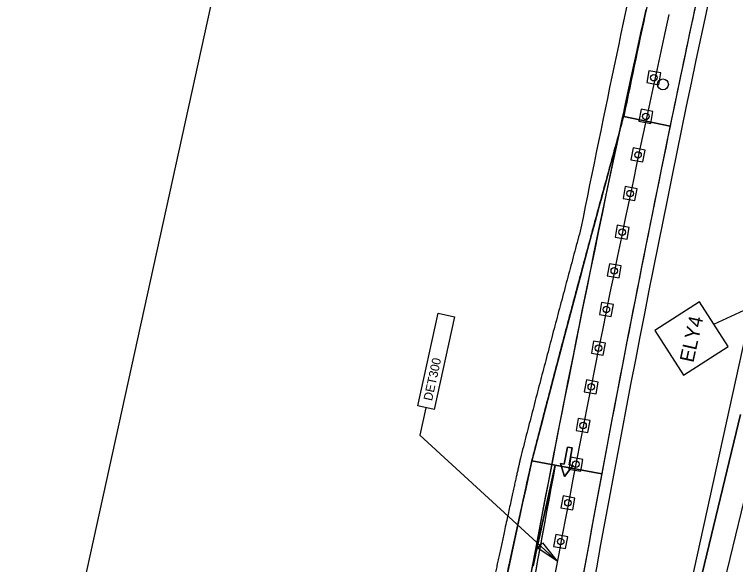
# Model space of a CAD drawing. Extents: x 14104283 to 14121738, y 8635219 to 8671666.
# Drawn here: x 14107783.5 to 14108149.2, y 8640616.4 to 8640895.4 of the extents above; entities that cross this region are included whole.
import ezdxf

# ---------------------------------------------------------------- set-up
doc = ezdxf.new("R2010")
doc.units = 0
for name, color, linetype in [('Cell', 7, 'Continuous'), ('Default', 7, 'Continuous'), ('dsnNonPlotable', 7, 'Continuous'), ('dsnPaintExistingBrokenLaneLineWhite', 7, 'Continuous'), ('dsnPaintExistingEdgeLineRightWhite', 7, 'Continuous'), ('dsnStdLabel', 7, 'Continuous'), ('dsnStgShadingPrevPav', 7, 'Continuous'), ('dsnTapePlaceChannelizingLaneWhite', 7, 'Continuous'), ('dsnTapePlaceChannelizingLaneYellow', 7, 'Continuous'), ('Text', 7, 'Continuous')]:
    doc.layers.add(name, color=color, linetype=linetype)

msp = doc.modelspace()

# ---------------------------------------------------------------- linework, layer by layer
at = {"layer": 'Cell'}
for points in [[(14108110.21, 8640859.76), (14108111.29, 8640865.79), (14108105.26, 8640866.87), (14108104.18, 8640860.84), (14108110.21, 8640859.76)], [(14108110.21, 8640859.76), (14108111.29, 8640865.79), (14108105.26, 8640866.87), (14108104.18, 8640860.84), (14108110.21, 8640859.76)], [(14108106.19, 8640840.17), (14108107.27, 8640846.2), (14108101.24, 8640847.28), (14108100.16, 8640841.25), (14108106.19, 8640840.17)], [(14108106.19, 8640840.17), (14108107.27, 8640846.2), (14108101.24, 8640847.28), (14108100.16, 8640841.25), (14108106.19, 8640840.17)], [(14108102.18, 8640820.58), (14108103.26, 8640826.61), (14108097.23, 8640827.69), (14108096.15, 8640821.66), (14108102.18, 8640820.58)], [(14108102.18, 8640820.58), (14108103.26, 8640826.61), (14108097.23, 8640827.69), (14108096.15, 8640821.66), (14108102.18, 8640820.58)], [(14108098.17, 8640800.98), (14108099.25, 8640807.01), (14108093.22, 8640808.09), (14108092.14, 8640802.06), (14108098.17, 8640800.98)], [(14108098.17, 8640800.98), (14108099.25, 8640807.01), (14108093.22, 8640808.09), (14108092.14, 8640802.06), (14108098.17, 8640800.98)], [(14108094.16, 8640781.39), (14108095.24, 8640787.42), (14108089.21, 8640788.5), (14108088.13, 8640782.47), (14108094.16, 8640781.39)], [(14108094.16, 8640781.39), (14108095.24, 8640787.42), (14108089.21, 8640788.5), (14108088.13, 8640782.47), (14108094.16, 8640781.39)], [(14108090.14, 8640761.8), (14108091.22, 8640767.83), (14108085.19, 8640768.91), (14108084.11, 8640762.88), (14108090.14, 8640761.8)], [(14108090.14, 8640761.8), (14108091.22, 8640767.83), (14108085.19, 8640768.91), (14108084.11, 8640762.88), (14108090.14, 8640761.8)], [(14108086.13, 8640742.2), (14108087.21, 8640748.23), (14108081.18, 8640749.31), (14108080.1, 8640743.28), (14108086.13, 8640742.2)], [(14108086.13, 8640742.2), (14108087.21, 8640748.23), (14108081.18, 8640749.31), (14108080.1, 8640743.28), (14108086.13, 8640742.2)], [(14108082.12, 8640722.61), (14108083.2, 8640728.64), (14108077.17, 8640729.72), (14108076.09, 8640723.69), (14108082.12, 8640722.61)], [(14108082.12, 8640722.61), (14108083.2, 8640728.64), (14108077.17, 8640729.72), (14108076.09, 8640723.69), (14108082.12, 8640722.61)], [(14108078.5, 8640702.94), (14108079.58, 8640708.97), (14108073.55, 8640710.05), (14108072.47, 8640704.02), (14108078.5, 8640702.94)], [(14108078.5, 8640702.94), (14108079.58, 8640708.97), (14108073.55, 8640710.05), (14108072.47, 8640704.02), (14108078.5, 8640702.94)], [(14108074.32, 8640683.37), (14108075.4, 8640689.4), (14108069.37, 8640690.48), (14108068.29, 8640684.45), (14108074.32, 8640683.37)], [(14108074.32, 8640683.37), (14108075.4, 8640689.4), (14108069.37, 8640690.48), (14108068.29, 8640684.45), (14108074.32, 8640683.37)], [(14108062.33, 8640667.36), (14108060.48, 8640667.69), (14108062.44, 8640660.99), (14108066.63, 8640666.58), (14108064.79, 8640666.91), (14108066.35, 8640675.52), (14108063.89, 8640675.97), (14108062.33, 8640667.36)], [(14108070.65, 8640663.71), (14108071.73, 8640669.74), (14108065.7, 8640670.82), (14108064.62, 8640664.79), (14108070.65, 8640663.71)], [(14108070.65, 8640663.71), (14108071.73, 8640669.74), (14108065.7, 8640670.82), (14108064.62, 8640664.79), (14108070.65, 8640663.71)], [(14108066.65, 8640644.12), (14108067.73, 8640650.15), (14108061.7, 8640651.22), (14108060.62, 8640645.2), (14108066.65, 8640644.12)], [(14108066.65, 8640644.12), (14108067.73, 8640650.15), (14108061.7, 8640651.22), (14108060.62, 8640645.2), (14108066.65, 8640644.12)], [(14108062.97, 8640624.46), (14108064.05, 8640630.49), (14108058.02, 8640631.57), (14108056.94, 8640625.54), (14108062.97, 8640624.46)], [(14108062.97, 8640624.46), (14108064.05, 8640630.49), (14108058.02, 8640631.57), (14108056.94, 8640625.54), (14108062.97, 8640624.46)]]:
    msp.add_lwpolyline(points, dxfattribs=at)
msp.add_lwpolyline([(14108063.89, 8640675.97), (14108066.35, 8640675.52), (14108064.79, 8640666.91), (14108066.63, 8640666.58), (14108062.44, 8640660.99), (14108060.48, 8640667.69), (14108062.33, 8640667.36)], close=True, dxfattribs=at)
for centre, radius in [((14108107.73, 8640863.32), 1.65), ((14108107.73, 8640863.32), 1.65), ((14108112.34, 8640859.94), 2.75), ((14108103.72, 8640843.72), 1.65), ((14108103.72, 8640843.72), 1.65), ((14108099.71, 8640824.13), 1.65), ((14108099.71, 8640824.13), 1.65), ((14108095.69, 8640804.54), 1.65), ((14108095.69, 8640804.54), 1.65), ((14108091.68, 8640784.94), 1.65), ((14108091.68, 8640784.94), 1.65), ((14108087.67, 8640765.35), 1.65), ((14108087.67, 8640765.35), 1.65), ((14108083.66, 8640745.76), 1.65), ((14108083.66, 8640745.76), 1.65), ((14108079.64, 8640726.16), 1.65), ((14108079.64, 8640726.16), 1.65), ((14108076.02, 8640706.49), 1.65), ((14108076.02, 8640706.49), 1.65), ((14108071.85, 8640686.93), 1.65), ((14108071.85, 8640686.93), 1.65), ((14108068.17, 8640667.27), 1.65), ((14108068.17, 8640667.27), 1.65), ((14108064.17, 8640647.67), 1.65), ((14108064.17, 8640647.67), 1.65), ((14108060.5, 8640628.01), 1.65), ((14108060.5, 8640628.01), 1.65)]:
    msp.add_circle(centre, radius, dxfattribs=at)
at = {"layer": 'Default'}
for p, q in [((14108151.72, 8640692.57), (14108081.5, 8640400.87)), ((14108093.19, 8640398.18), (14108163.38, 8640689.76))]:
    msp.add_line(p, q, dxfattribs=at)
for centre, radius, start, end in [((14117394.14, 8638857.08), 9512, 167.610212, 171.325989), ((14117394.14, 8638857.08), 9500, 167.610212, 171.325989), ((14117502.5, 8638839.63), 9621.75, 168.048489, 169.460498), ((14117245.13, 8638308.71), 9497.18, 164.591267, 165.609485), ((14117342.69, 8638609.63), 9522.13, 167.509575, 168.915877)]:
    msp.add_arc(centre, radius, start, end, dxfattribs=at)
at = {"layer": 'dsnNonPlotable'}
msp.add_lwpolyline([(14107651.31, 8639844.94), (14107987.7, 8641375.92), (14108480.93, 8641267.54), (14108144.54, 8639736.56)], close=True, dxfattribs=at)
at = {"layer": 'dsnPaintExistingBrokenLaneLineWhite'}
msp.add_arc((14117394.14, 8638857.08), 9500, 167.610212, 171.325989, dxfattribs=at)
at = {"layer": 'dsnPaintExistingEdgeLineRightWhite'}
for centre, radius, start, end in [((14117394.14, 8638857.08), 9512, 167.610212, 168.003119), ((14117245.13, 8638308.71), 9497.18, 164.578206, 165.609485), ((14117342.69, 8638609.63), 9522.13, 167.509575, 168.915877)]:
    msp.add_arc(centre, radius, start, end, dxfattribs=at)
at = {"layer": 'dsnStdLabel'}
msp.add_line((14108138.22, 8640738.34), (14108165.33, 8640750.93), dxfattribs=at)
msp.add_lwpolyline([(14108122.75, 8640712.41), (14108145.49, 8640726.96), (14108130.94, 8640749.71), (14108108.2, 8640735.16)], close=True, dxfattribs=at)
at = {"layer": 'dsnStgShadingPrevPav'}
for p, q in [((14108092.51, 8640843.67), (14108116.01, 8640838.82)), ((14108116.01, 8640838.82), (14108092.51, 8640843.67)), ((14108045.92, 8640669.04), (14108057.72, 8640666.84)), ((14108081.31, 8640662.43), (14108045.92, 8640669.04)), ((14108057.72, 8640666.84), (14108081.31, 8640662.43))]:
    msp.add_line(p, q, dxfattribs=at)
msp.add_lwpolyline([(14108081.5, 8640400.87), (14108123.34, 8640591.33), (14108126.55, 8640605.98), (14108216.67, 8641016.2), (14108268.16, 8641250.61), (14108382.95, 8641773.15), (14108422.02, 8641764.57), (14108309.38, 8641251.8), (14108270.22, 8641073.55), (14108265.93, 8641054.01), (14108255.74, 8641007.62), (14108202.1, 8640763.44), (14108120.56, 8640392.29)], close=True, dxfattribs=at)
for radius, start, end in [(9522, 167.610212, 168.688952), (9512, 167.610212, 168.328257), (9512, 167.610212, 168.328257), (9488, 167.610212, 172.222077), (9482, 167.610212, 172.222077), (9488, 167.610212, 168.328257), (9488, 168.328257, 169.413861), (9512, 169.413861, 172.222077), (9512, 169.413861, 170.574102), (9488, 169.413861, 172.222077)]:
    msp.add_arc((14117407.82, 8638919.35), radius, start, end, dxfattribs=at)
for points, degree in [([(14108045.92, 8640669.04), (14108046.67, 8640671.96), (14108048.17, 8640677.8), (14108050.43, 8640686.55), (14108052.7, 8640695.31), (14108054.98, 8640704.06), (14108057.26, 8640712.8), (14108059.55, 8640721.55), (14108061.85, 8640730.29), (14108064.16, 8640739.03), (14108066.48, 8640747.76), (14108068.81, 8640756.5), (14108071.14, 8640765.23), (14108073.48, 8640773.95), (14108075.83, 8640782.68), (14108078.19, 8640791.4), (14108080.55, 8640800.12), (14108082.93, 8640808.84), (14108085.31, 8640817.55), (14108087.7, 8640826.26), (14108090.1, 8640834.97), (14108091.7, 8640840.77), (14108092.51, 8640843.67)], 3), ([(14108045.92, 8640669.04), (14108046.67, 8640671.96), (14108048.17, 8640677.8), (14108050.43, 8640686.55), (14108052.7, 8640695.31), (14108054.98, 8640704.06), (14108057.26, 8640712.8), (14108059.55, 8640721.55), (14108061.85, 8640730.29), (14108064.16, 8640739.03), (14108066.48, 8640747.76), (14108068.81, 8640756.5), (14108071.14, 8640765.23), (14108073.48, 8640773.95), (14108075.83, 8640782.68), (14108078.19, 8640791.4), (14108080.55, 8640800.12), (14108082.93, 8640808.84), (14108085.31, 8640817.55), (14108087.7, 8640826.26), (14108090.1, 8640834.97), (14108091.7, 8640840.77), (14108092.51, 8640843.67)], 3), ([(14108070.77, 8640786.95), (14108070.25, 8640785.01), (14108069.2, 8640781.13), (14108067.63, 8640775.31), (14108066.07, 8640769.49), (14108064.51, 8640763.67), (14108062.96, 8640757.84), (14108061.41, 8640752.02), (14108059.86, 8640746.19), (14108058.31, 8640740.36), (14108056.77, 8640734.54), (14108055.23, 8640728.71), (14108053.7, 8640722.87), (14108052.17, 8640717.04), (14108050.64, 8640711.21), (14108049.12, 8640705.37), (14108047.6, 8640699.54), (14108046.09, 8640693.7), (14108044.58, 8640687.86), (14108043.07, 8640682.02), (14108041.56, 8640676.18), (14108040.56, 8640672.28), (14108040.06, 8640670.34)], 3), ([(14108040.07, 8640670.33), (14108039.11, 8640666.01), (14108035.79, 8640651.03), (14108029.85, 8640623.7), (14108025.19, 8640602.04), (14108020.26, 8640578.84), (14108015.47, 8640556.04), (14108010.72, 8640533.12), (14108006.03, 8640510.22), (14108001.39, 8640487.29), (14107996.81, 8640464.36), (14107992.28, 8640441.41), (14107987.82, 8640418.46), (14107983.4, 8640395.49), (14107979.05, 8640372.51), (14107974.75, 8640349.53), (14107970.51, 8640326.51), (14107966.33, 8640303.59), (14107962.15, 8640280.24), (14107958.29, 8640258.43), (14107953.48, 8640230.88), (14107950.9, 8640215.75), (14107950.15, 8640211.39)], 2), ([(14107956.07, 8640210.37), (14107957.38, 8640218.06), (14107960.02, 8640233.43), (14107964.04, 8640256.47), (14107968.11, 8640279.5), (14107972.24, 8640302.51), (14107976.42, 8640325.52), (14107980.66, 8640348.51), (14107984.96, 8640371.49), (14107989.32, 8640394.46), (14107993.73, 8640417.41), (14107998.19, 8640440.35), (14108002.71, 8640463.28), (14108007.29, 8640486.2), (14108011.92, 8640509.1), (14108016.61, 8640531.99), (14108021.36, 8640554.87), (14108026.16, 8640577.73), (14108031.01, 8640600.58), (14108035.93, 8640623.41), (14108040.89, 8640646.24), (14108044.25, 8640661.44), (14108045.92, 8640669.04)], 3), ([(14108045.17, 8640665.62), (14108045.34, 8640666.38), (14108045.5, 8640667.14), (14108045.67, 8640667.9)], 2), ([(14108045.67, 8640667.9), (14108045.76, 8640668.28), (14108045.84, 8640668.66), (14108045.92, 8640669.04)], 2), ([(14108057.72, 8640666.84), (14108057.64, 8640666.46), (14108057.55, 8640666.08), (14108057.47, 8640665.7)], 2), ([(14108057.47, 8640665.7), (14108057.55, 8640666.08), (14108057.64, 8640666.46), (14108057.72, 8640666.84)], 2), ([(14108043.91, 8640659.92), (14108044.16, 8640661.06), (14108044.41, 8640662.2), (14108044.67, 8640663.34)], 2), ([(14108044.67, 8640663.34), (14108044.75, 8640663.72), (14108044.83, 8640664.1), (14108044.92, 8640664.48)], 2), ([(14108044.92, 8640664.48), (14108045, 8640664.86), (14108045.09, 8640665.24), (14108045.17, 8640665.62)], 2), ([(14108056.97, 8640663.42), (14108056.88, 8640663.04), (14108056.8, 8640662.66), (14108056.71, 8640662.28)], 2), ([(14108056.71, 8640662.28), (14108056.8, 8640662.66), (14108056.88, 8640663.04), (14108056.97, 8640663.42)], 2), ([(14108057.22, 8640664.56), (14108057.13, 8640664.18), (14108057.05, 8640663.8), (14108056.97, 8640663.42)], 2), ([(14108056.97, 8640663.42), (14108057.05, 8640663.8), (14108057.13, 8640664.18), (14108057.22, 8640664.56)], 2), ([(14108057.47, 8640665.7), (14108057.38, 8640665.32), (14108057.3, 8640664.94), (14108057.22, 8640664.56)], 2), ([(14108057.22, 8640664.56), (14108057.3, 8640664.94), (14108057.38, 8640665.32), (14108057.47, 8640665.7)], 2), ([(14108043.66, 8640658.78), (14108043.74, 8640659.16), (14108043.83, 8640659.54), (14108043.91, 8640659.92)], 2), ([(14108056.71, 8640662.28), (14108056.46, 8640661.14), (14108056.21, 8640660), (14108055.96, 8640658.87)], 2), ([(14108055.96, 8640658.87), (14108056.21, 8640660), (14108056.46, 8640661.14), (14108056.71, 8640662.28)], 2), ([(14108042.91, 8640655.36), (14108043.07, 8640656.12), (14108043.24, 8640656.88), (14108043.41, 8640657.64)], 2), ([(14108043.41, 8640657.64), (14108043.49, 8640658.02), (14108043.58, 8640658.4), (14108043.66, 8640658.78)], 2), ([(14108055.71, 8640657.73), (14108055.21, 8640655.45), (14108054.7, 8640653.17), (14108054.2, 8640650.89)], 2), ([(14108054.2, 8640650.89), (14108054.7, 8640653.17), (14108055.21, 8640655.45), (14108055.71, 8640657.73)], 2), ([(14108055.96, 8640658.87), (14108055.88, 8640658.49), (14108055.79, 8640658.11), (14108055.71, 8640657.73)], 2), ([(14108055.71, 8640657.73), (14108055.79, 8640658.11), (14108055.88, 8640658.49), (14108055.96, 8640658.87)], 2), ([(14108041.9, 8640650.8), (14108041.99, 8640651.18), (14108042.07, 8640651.56), (14108042.15, 8640651.94)], 2), ([(14108042.15, 8640651.94), (14108042.4, 8640653.08), (14108042.65, 8640654.22), (14108042.91, 8640655.36)], 2), ([(14108041.15, 8640647.37), (14108041.23, 8640647.76), (14108041.32, 8640648.14), (14108041.4, 8640648.52)], 2), ([(14108041.4, 8640648.52), (14108041.48, 8640648.9), (14108041.57, 8640649.28), (14108041.65, 8640649.66)], 2), ([(14108041.65, 8640649.66), (14108041.74, 8640650.04), (14108041.82, 8640650.42), (14108041.9, 8640650.8)], 2), ([(14108053.7, 8640648.62), (14108053.62, 8640648.24), (14108053.54, 8640647.86), (14108053.45, 8640647.48)], 2), ([(14108053.45, 8640647.48), (14108053.54, 8640647.86), (14108053.62, 8640648.24), (14108053.7, 8640648.62)], 2), ([(14108053.95, 8640649.75), (14108053.87, 8640649.37), (14108053.79, 8640648.99), (14108053.7, 8640648.62)], 2), ([(14108053.7, 8640648.62), (14108053.79, 8640648.99), (14108053.87, 8640649.37), (14108053.95, 8640649.75)], 2), ([(14108054.2, 8640650.89), (14108054.12, 8640650.51), (14108054.04, 8640650.13), (14108053.95, 8640649.75)], 2), ([(14108053.95, 8640649.75), (14108054.04, 8640650.13), (14108054.12, 8640650.51), (14108054.2, 8640650.89)], 2), ([(14108039.9, 8640641.67), (14108040.15, 8640642.81), (14108040.4, 8640643.95), (14108040.65, 8640645.09)], 2), ([(14108040.65, 8640645.09), (14108040.73, 8640645.47), (14108040.82, 8640645.85), (14108040.9, 8640646.23)], 2), ([(14108040.9, 8640646.23), (14108040.98, 8640646.61), (14108041.07, 8640646.99), (14108041.15, 8640647.37)], 2), ([(14108052.95, 8640645.2), (14108052.87, 8640644.82), (14108052.79, 8640644.44), (14108052.7, 8640644.06)], 2), ([(14108052.7, 8640644.06), (14108052.79, 8640644.44), (14108052.87, 8640644.82), (14108052.95, 8640645.2)], 2), ([(14108053.45, 8640647.48), (14108053.29, 8640646.72), (14108053.12, 8640645.96), (14108052.95, 8640645.2)], 2), ([(14108052.95, 8640645.2), (14108053.12, 8640645.96), (14108053.29, 8640646.72), (14108053.45, 8640647.48)], 2), ([(14108039.16, 8640638.25), (14108039.4, 8640639.39), (14108039.65, 8640640.53), (14108039.9, 8640641.67)], 2), ([(14108052.7, 8640644.06), (14108052.45, 8640642.92), (14108052.2, 8640641.78), (14108051.95, 8640640.64)], 2), ([(14108051.95, 8640640.64), (14108052.2, 8640641.78), (14108052.45, 8640642.92), (14108052.7, 8640644.06)], 2), ([(14108038.91, 8640637.11), (14108038.99, 8640637.49), (14108039.07, 8640637.87), (14108039.16, 8640638.25)], 2), ([(14108051.46, 8640638.36), (14108051.04, 8640636.46), (14108050.63, 8640634.56), (14108050.21, 8640632.66)], 2), ([(14108050.21, 8640632.66), (14108050.63, 8640634.56), (14108051.04, 8640636.46), (14108051.46, 8640638.36)], 2), ([(14108051.7, 8640639.5), (14108051.62, 8640639.12), (14108051.54, 8640638.74), (14108051.46, 8640638.36)], 2), ([(14108051.46, 8640638.36), (14108051.54, 8640638.74), (14108051.62, 8640639.12), (14108051.7, 8640639.5)], 2), ([(14108051.95, 8640640.64), (14108051.87, 8640640.26), (14108051.79, 8640639.88), (14108051.7, 8640639.5)], 2), ([(14108051.7, 8640639.5), (14108051.79, 8640639.88), (14108051.87, 8640640.26), (14108051.95, 8640640.64)], 2), ([(14108037.42, 8640630.26), (14108037.75, 8640631.78), (14108038.08, 8640633.3), (14108038.41, 8640634.83)], 2), ([(14108038.41, 8640634.83), (14108038.49, 8640635.21), (14108038.58, 8640635.59), (14108038.66, 8640635.97)], 2), ([(14108038.66, 8640635.97), (14108038.74, 8640636.35), (14108038.82, 8640636.73), (14108038.91, 8640637.11)], 2), ([(14108037.17, 8640629.12), (14108037.25, 8640629.5), (14108037.34, 8640629.88), (14108037.42, 8640630.26)], 2), ([(14108049.97, 8640631.52), (14108049.22, 8640628.11), (14108048.48, 8640624.69), (14108047.74, 8640621.27)], 2), ([(14108047.74, 8640621.27), (14108048.48, 8640624.69), (14108049.22, 8640628.11), (14108049.97, 8640631.52)], 2), ([(14108050.21, 8640632.66), (14108050.13, 8640632.28), (14108050.05, 8640631.9), (14108049.97, 8640631.52)], 2), ([(14108049.97, 8640631.52), (14108050.05, 8640631.9), (14108050.13, 8640632.28), (14108050.21, 8640632.66)], 2), ([(14108036.43, 8640625.7), (14108036.51, 8640626.08), (14108036.59, 8640626.46), (14108036.68, 8640626.84)], 2), ([(14108036.68, 8640626.84), (14108036.84, 8640627.6), (14108037.01, 8640628.36), (14108037.17, 8640629.12)], 2), ([(14108035.19, 8640619.99), (14108035.44, 8640621.13), (14108035.69, 8640622.27), (14108035.93, 8640623.41)], 2), ([(14108035.93, 8640623.41), (14108036.02, 8640623.79), (14108036.1, 8640624.17), (14108036.18, 8640624.55)], 2), ([(14108036.18, 8640624.55), (14108036.26, 8640624.93), (14108036.35, 8640625.32), (14108036.43, 8640625.7)], 2), ([(14108034.45, 8640616.56), (14108034.7, 8640617.71), (14108034.95, 8640618.85), (14108035.19, 8640619.99)], 2), ([(14108047.25, 8640618.99), (14108047.17, 8640618.61), (14108047.08, 8640618.23), (14108047, 8640617.85)], 2), ([(14108047, 8640617.85), (14108047.08, 8640618.23), (14108047.17, 8640618.61), (14108047.25, 8640618.99)], 2), ([(14108047.49, 8640620.13), (14108047.41, 8640619.75), (14108047.33, 8640619.37), (14108047.25, 8640618.99)], 2), ([(14108047.25, 8640618.99), (14108047.33, 8640619.37), (14108047.41, 8640619.75), (14108047.49, 8640620.13)], 2), ([(14108047.74, 8640621.27), (14108047.66, 8640620.89), (14108047.58, 8640620.51), (14108047.49, 8640620.13)], 2), ([(14108047.49, 8640620.13), (14108047.58, 8640620.51), (14108047.66, 8640620.89), (14108047.74, 8640621.27)], 2), ([(14108034.21, 8640615.42), (14108034.29, 8640615.8), (14108034.37, 8640616.18), (14108034.45, 8640616.56)], 2), ([(14108046.75, 8640616.71), (14108046.67, 8640616.33), (14108046.59, 8640615.95), (14108046.51, 8640615.57)], 2), ([(14108046.51, 8640615.57), (14108046.59, 8640615.95), (14108046.67, 8640616.33), (14108046.75, 8640616.71)], 2), ([(14108047, 8640617.85), (14108046.92, 8640617.47), (14108046.84, 8640617.09), (14108046.75, 8640616.71)], 2), ([(14108046.75, 8640616.71), (14108046.84, 8640617.09), (14108046.92, 8640617.47), (14108047, 8640617.85)], 2)]:
    msp.add_open_spline(points, degree=degree, dxfattribs=at)
at = {"layer": 'dsnTapePlaceChannelizingLaneWhite'}
msp.add_line((14108093.19, 8640398.18), (14108163.38, 8640689.76), dxfattribs=at)
at = {"layer": 'dsnTapePlaceChannelizingLaneYellow'}
msp.add_line((14108081.5, 8640400.87), (14108151.72, 8640692.57), dxfattribs=at)
at = {"layer": 'Text'}
for points in [[(14107988.06, 8640696.85), (14107998.39, 8640743.84), (14108006.59, 8640742.04), (14107996.27, 8640695.05)], [(14107988.06, 8640696.85), (14107998.39, 8640743.84), (14108006.59, 8640742.04), (14107996.27, 8640695.05)], [(14108058.79, 8640618.1), (14108048.88, 8640624.77), (14108051.28, 8640627.38)]]:
    msp.add_lwpolyline(points, close=True, dxfattribs=at)
msp.add_lwpolyline([(14107992.16, 8640695.95), (14107989.01, 8640682), (14108058.79, 8640618.1)], dxfattribs=at)

# ---------------------------------------------------------------- texts
at = {"layer": 'dsnStdLabel'}
msp.add_text('ELY4', height=7.2, rotation=77.6078, dxfattribs=at).set_placement((14108127.77, 8640718.51))
at = {"layer": 'Text'}
msp.add_text('DET300', height=4.484, rotation=77.6078, dxfattribs=at).set_placement((14107995.23, 8640699.16))

doc.saveas('drawing.dxf')
